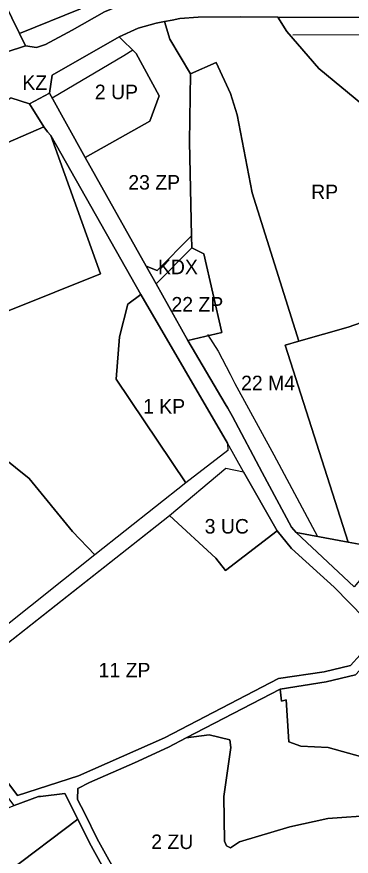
# Model space of a CAD drawing. Extents: x 7437831 to 7440315, y 5545798 to 5547888.
# Drawn here: x 7438704 to 7438934, y 5546989 to 5547567 of the extents above; entities that cross this region are included whole.
import ezdxf

# ---------------------------------------------------------------- set-up
doc = ezdxf.new("R2010")
doc.units = 0
for name, color, linetype in [('linie_rozgraniczajace', 7, 'Continuous'), ('linie_zabudowy_nieprzekraczalne', 7, 'Continuous'), ('oznaczenia_przeznaczen', 7, 'Continuous')]:
    doc.layers.add(name, color=color, linetype=linetype)

msp = doc.modelspace()

# ---------------------------------------------------------------- linework, layer by layer
at = {"layer": 'linie_rozgraniczajace'}
for points in [[(7438606.06, 5547740.36), (7438616.2, 5547745.65), (7438634.59, 5547709.28), (7438689.67, 5547587.65), (7438705.7, 5547555.05), (7438709.92, 5547546.46), (7438696.45, 5547542.1), (7438696.46, 5547542.13), (7438625.32, 5547700.8)], [(7438732.6, 5547606.48), (7438747.71, 5547572.08), (7438705.7, 5547555.05), (7438689.67, 5547587.65)], [(7438828.96, 5547566.29), (7438858.2, 5547566.45), (7438883.67, 5547566.33), (7438889.93, 5547556.37), (7438911.91, 5547531.01), (7438942.2, 5547505.98), (7438953.96, 5547489.8), (7438941.06, 5547484.22), (7438951.02, 5547437.82), (7438971.24, 5547412.38), (7439016.84, 5547383.23), (7438955.2, 5547361.08), (7438932.28, 5547352.94), (7438898.23, 5547343.32), (7438865.97, 5547445.48), (7438855.72, 5547499.1), (7438851.23, 5547513.66), (7438841.19, 5547535.01), (7438823.53, 5547527.36), (7438809.33, 5547551.21), (7438805.74, 5547563.28), (7438810.97, 5547564.3), (7438816.19, 5547565.31)], [(7438805.74, 5547563.28), (7438809.33, 5547551.21), (7438823.53, 5547527.36), (7438822.78, 5547480.48), (7438824.16, 5547415.8), (7438800.6, 5547391.95), (7438793.04, 5547394.95), (7438750.87, 5547469.7), (7438795.57, 5547494.62), (7438801.97, 5547512.06), (7438786.07, 5547541.18), (7438774.45, 5547552.84), (7438787.42, 5547558.81), (7438799.87, 5547562.14)], [(7438774.45, 5547552.84), (7438786.07, 5547541.18), (7438801.97, 5547512.06), (7438795.57, 5547494.62), (7438750.87, 5547469.7), (7438726.51, 5547513.97), (7438728.23, 5547526.47)], [(7438841.19, 5547535.01), (7438851.23, 5547513.66), (7438855.72, 5547499.1), (7438865.97, 5547445.48), (7438898.23, 5547343.32), (7438888.7, 5547340.63), (7438932.24, 5547204.92), (7438896.31, 5547211.65), (7438893.1, 5547215.3), (7438873.02, 5547253.01), (7438852.56, 5547291.43), (7438849.22, 5547297.1), (7438847.46, 5547300.08), (7438821.69, 5547343.78), (7438845.09, 5547349.23), (7438832.73, 5547403.32), (7438824.53, 5547407.63), (7438824.16, 5547415.8), (7438822.78, 5547480.48), (7438823.53, 5547527.36)], [(7438699.75, 5547510.84), (7438712.64, 5547506.6), (7438722.4, 5547490.74), (7438593.34, 5547434.76), (7438613.41, 5547448.63), (7438625.38, 5547457.2), (7438640.9, 5547469.76), (7438663.92, 5547487), (7438679.84, 5547498.62)], [(7438722.4, 5547490.74), (7438725.13, 5547487.44), (7438727.23, 5547484.89), (7438761.65, 5547389.7), (7438698.57, 5547364.49), (7438693.49, 5547367.72), (7438531, 5547359.42), (7438513.39, 5547400.09), (7438514.47, 5547400.55), (7438555.04, 5547418.15), (7438593.34, 5547434.76)], [(7438727.23, 5547484.89), (7438789.42, 5547375.34), (7438780.33, 5547368.67), (7438774.72, 5547346.24), (7438772.34, 5547317.22), (7438820.4, 5547245.87), (7438757.71, 5547196.2), (7438742.17, 5547212.37), (7438712.49, 5547248.75), (7438685.01, 5547270.7), (7438624.61, 5547291.93), (7438552.21, 5547301.15), (7438490.81, 5547300.6), (7438471.73, 5547380.6), (7438473.61, 5547387.34), (7438513.39, 5547400.09), (7438531, 5547359.42), (7438693.49, 5547367.72), (7438698.57, 5547364.49), (7438761.65, 5547389.7)], [(7438824.16, 5547415.8), (7438824.53, 5547407.63), (7438799.93, 5547382.73), (7438793.04, 5547394.95), (7438800.6, 5547391.95)], [(7438824.53, 5547407.63), (7438832.73, 5547403.32), (7438845.09, 5547349.23), (7438821.69, 5547343.78), (7438799.93, 5547382.73)], [(7438789.42, 5547375.34), (7438849.04, 5547273.06), (7438849.23, 5547267.96), (7438820.4, 5547245.87), (7438772.34, 5547317.22), (7438774.72, 5547346.24), (7438780.33, 5547368.67)], [(7438955.2, 5547361.08), (7439026.61, 5547228.25), (7439014.66, 5547218.74), (7438989.33, 5547202.5), (7438977.77, 5547198.98), (7438965.14, 5547198.94), (7438932.24, 5547204.92), (7438888.7, 5547340.63), (7438898.23, 5547343.32), (7438932.28, 5547352.94)], [(7439075.64, 5547315.72), (7439083.79, 5547297.7), (7439150.54, 5547208.32), (7439157.59, 5547202.13), (7439145.18, 5547197.27), (7439107.47, 5547188.91), (7439088.31, 5547197.19), (7439052.98, 5547221.74), (7439038.94, 5547218.77), (7438988.47, 5547187.22), (7438967.95, 5547184.39), (7438948.84, 5547188.98), (7438936.39, 5547174.36), (7438896.31, 5547211.65), (7438932.24, 5547204.92), (7438965.14, 5547198.94), (7438977.77, 5547198.98), (7438989.33, 5547202.5), (7439014.66, 5547218.74), (7439026.61, 5547228.25), (7439044.3, 5547241.89), (7439070.18, 5547239.54), (7439068.06, 5547265.64), (7439052.3, 5547305.33)], [(7438490.81, 5547300.6), (7438552.21, 5547301.15), (7438624.61, 5547291.93), (7438685.01, 5547270.7), (7438712.49, 5547248.75), (7438742.17, 5547212.37), (7438757.71, 5547196.2), (7438647.09, 5547108.46), (7438602.14, 5547134.21), (7438589.94, 5547144.27), (7438569.38, 5547166.56), (7438543.43, 5547200.86), (7438499.99, 5547267.38)], [(7438809.04, 5547223.28), (7438847.87, 5547255.92), (7438860.06, 5547253.49), (7438883.2, 5547212.78), (7438847.73, 5547185.6), (7438841.11, 5547194.03)], [(7438809.04, 5547223.28), (7438841.11, 5547194.03), (7438847.73, 5547185.6), (7438883.2, 5547212.78), (7438893.1, 5547200.63), (7438912.87, 5547182.74), (7438922.54, 5547173.99), (7438953.8, 5547142.07), (7438933.7, 5547120.16), (7438915.71, 5547115.81), (7438884.23, 5547111.26), (7438805.66, 5547070.29), (7438746.38, 5547044.16), (7438704.39, 5547030.75), (7438652.23, 5547099.85), (7438735.45, 5547165.35), (7438790.4, 5547208.6)]]:
    msp.add_lwpolyline(points, close=True, dxfattribs=at)
for points in [[(7438705.7, 5547555.05), (7438747.71, 5547572.08), (7438732.6, 5547606.48), (7438758.97, 5547620.75), (7438765.23, 5547625.53)], [(7438696.45, 5547542.1), (7438709.92, 5547546.46), (7438717.49, 5547545.42), (7438723.59, 5547547.38), (7438741.99, 5547557.3), (7438764.42, 5547569.93), (7438781.17, 5547576.86), (7438795.62, 5547581.06)], [(7438795.62, 5547581.06), (7438781.17, 5547576.86), (7438764.42, 5547569.93), (7438741.99, 5547557.3), (7438723.59, 5547547.38), (7438717.49, 5547545.42)], [(7438828.96, 5547566.29), (7438816.19, 5547565.31), (7438810.97, 5547564.3)], [(7438858.2, 5547566.45), (7438828.96, 5547566.29)], [(7438883.67, 5547566.33), (7438858.2, 5547566.45)], [(7439055.78, 5547565.86), (7439055.68, 5547565.95), (7438883.67, 5547566.33)], [(7438942.2, 5547505.98), (7438911.91, 5547531.01), (7438889.93, 5547556.37), (7438883.67, 5547566.33), (7439055.68, 5547565.95)], [(7438799.87, 5547562.14), (7438787.42, 5547558.81), (7438774.45, 5547552.84)], [(7438805.74, 5547563.28), (7438799.87, 5547562.14)], [(7438810.97, 5547564.3), (7438805.74, 5547563.28)], [(7438709.92, 5547546.46), (7438705.7, 5547555.05)], [(7438774.45, 5547552.84), (7438728.23, 5547526.47), (7438726.51, 5547513.97)], [(7438717.49, 5547545.42), (7438709.92, 5547546.46)], [(7438712.64, 5547506.6), (7438699.75, 5547510.84)], [(7438726.51, 5547513.97), (7438712.64, 5547506.6)], [(7438953.8, 5547142.07), (7438922.54, 5547173.99), (7438912.87, 5547182.74), (7438893.1, 5547200.63), (7438883.2, 5547212.78), (7438860.06, 5547253.49), (7438849.04, 5547273.06), (7438789.42, 5547375.34), (7438727.23, 5547484.89), (7438725.13, 5547487.44), (7438722.4, 5547490.74), (7438712.64, 5547506.6), (7438726.51, 5547513.97)], [(7438726.51, 5547513.97), (7438750.87, 5547469.7), (7438793.04, 5547394.95), (7438799.93, 5547382.73), (7438821.69, 5547343.78), (7438847.46, 5547300.08), (7438849.22, 5547297.1), (7438852.56, 5547291.43), (7438873.02, 5547253.01), (7438893.1, 5547215.3), (7438896.31, 5547211.65), (7438936.39, 5547174.36)], [(7438496.53, 5546979.31), (7438533.91, 5547005.79), (7438541.58, 5547011.8), (7438586.53, 5547048.24), (7438647.86, 5547095.7), (7438652.23, 5547099.85), (7438809.04, 5547223.28), (7438847.87, 5547255.92), (7438860.06, 5547253.49), (7438849.04, 5547273.06), (7438849.23, 5547267.96), (7438820.4, 5547245.87), (7438757.71, 5547196.2), (7438647.09, 5547108.46), (7438638.61, 5547101.68), (7438577.26, 5547053.66), (7438532.48, 5547017.36), (7438472.13, 5546971.37)], [(7438652.23, 5547099.85), (7438704.39, 5547030.75), (7438746.38, 5547044.16), (7438805.66, 5547070.29), (7438884.23, 5547111.26), (7438915.71, 5547115.81), (7438933.7, 5547120.16), (7438953.8, 5547142.07), (7438958.59, 5547136.94), (7438937.15, 5547113.6), (7438917, 5547108.92), (7438885.26, 5547103.9), (7438820.52, 5547070.25), (7438808.31, 5547063.92), (7438785.09, 5547053.09), (7438754.01, 5547039.54), (7438745.95, 5547035.56), (7438745.69, 5547027.85), (7438750.73, 5547018.27), (7438759.29, 5547000.75), (7438776.27, 5546970.26)], [(7438946.48, 5547055.89), (7438918.34, 5547063.78), (7438899.58, 5547064.68), (7438891.25, 5547067.6), (7438889.39, 5547096.5), (7438886.32, 5547095.53), (7438885.26, 5547103.9), (7438917, 5547108.92), (7438937.15, 5547113.6)], [(7438771.06, 5546967.29), (7438753.97, 5546997.98), (7438745.98, 5547014.32), (7438736.92, 5547032.02), (7438720.16, 5547030.07), (7438718.92, 5547029.93), (7438702.01, 5547023.71), (7438683.78, 5547047.94), (7438647.86, 5547095.7), (7438652.23, 5547099.85)], [(7438950.69, 5547017.22), (7438918.29, 5547014.78), (7438891.97, 5547009.16), (7438857.31, 5546998.81), (7438851.09, 5546994.55), (7438848.35, 5546996.1), (7438847.06, 5546999.11), (7438846.56, 5547029.94), (7438851.34, 5547063.66), (7438850.78, 5547068.96), (7438836.39, 5547072.39), (7438820.52, 5547070.25), (7438885.26, 5547103.9), (7438886.32, 5547095.53), (7438889.39, 5547096.5), (7438891.25, 5547067.6), (7438899.58, 5547064.68), (7438918.34, 5547063.78), (7438946.48, 5547055.89)], [(7438776.27, 5546970.26), (7438759.29, 5547000.75), (7438750.73, 5547018.27), (7438745.69, 5547027.85), (7438745.95, 5547035.56), (7438754.01, 5547039.54), (7438785.09, 5547053.09), (7438808.31, 5547063.92), (7438820.52, 5547070.25), (7438836.39, 5547072.39), (7438850.78, 5547068.96), (7438851.34, 5547063.66), (7438846.56, 5547029.94), (7438847.06, 5546999.11), (7438848.35, 5546996.1), (7438851.09, 5546994.55), (7438857.31, 5546998.81), (7438891.97, 5547009.16), (7438918.29, 5547014.78), (7438950.69, 5547017.22)], [(7438660.22, 5546985.37), (7438666.3, 5546989.94), (7438662.56, 5546994.72), (7438670.05, 5547000.07), (7438676.76, 5547010.19), (7438696.78, 5547021.72), (7438702.01, 5547023.71), (7438718.92, 5547029.93), (7438720.16, 5547030.07), (7438736.92, 5547032.02), (7438745.98, 5547014.32), (7438649.6, 5546941.86)], [(7438649.6, 5546941.86), (7438745.98, 5547014.32), (7438753.97, 5546997.98), (7438771.06, 5546967.29)]]:
    msp.add_lwpolyline(points, dxfattribs=at)
at = {"layer": 'linie_zabudowy_nieprzekraczalne'}
for points in [[(7439056.82, 5547555.41), (7438989.74, 5547554.31), (7438893.98, 5547553.98)], [(7438783.76, 5547543.5), (7438777.58, 5547539.58), (7438728.29, 5547510.55)], [(7438835.36, 5547347.91), (7438842.54, 5547336.45), (7438850.84, 5547320.64), (7438854.16, 5547314.21)], [(7438854.16, 5547314.21), (7438881, 5547265.12)], [(7438881, 5547265.12), (7438911.01, 5547208.9)]]:
    msp.add_lwpolyline(points, dxfattribs=at)

# ---------------------------------------------------------------- texts
at = {"layer": 'oznaczenia_przeznaczen'}
for s, p in [('KZ', (7438707.6821, 5547516.25)), ('2 UP', (7438757.6569, 5547509.83)), ('23 ZP', (7438780.7083, 5547447.62)), ('RP', (7438906.7232, 5547441.04)), ('KDX', (7438801.1443, 5547389.38)), ('22 ZP', (7438810.4583, 5547363.7)), ('22 M4', (7438858.4405, 5547309.54)), ('1 KP', (7438790.8653, 5547293.46)), ('3 UC', (7438833.3496, 5547210.91)), ('11 ZP', (7438760.2483, 5547111.92)), ('2 ZU', (7438796.4953, 5546993.8))]:
    msp.add_text(s, height=10, dxfattribs=at).set_placement(p)

doc.saveas('drawing.dxf')
